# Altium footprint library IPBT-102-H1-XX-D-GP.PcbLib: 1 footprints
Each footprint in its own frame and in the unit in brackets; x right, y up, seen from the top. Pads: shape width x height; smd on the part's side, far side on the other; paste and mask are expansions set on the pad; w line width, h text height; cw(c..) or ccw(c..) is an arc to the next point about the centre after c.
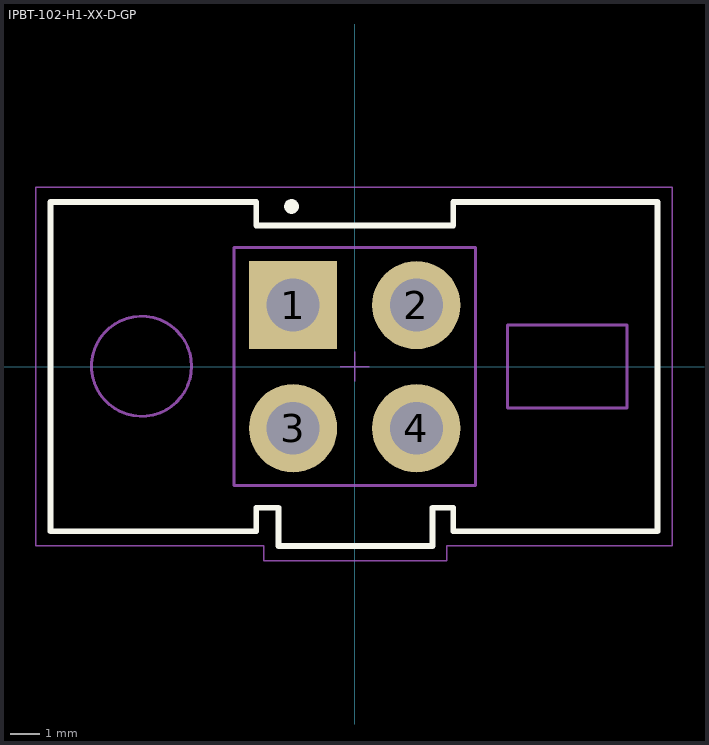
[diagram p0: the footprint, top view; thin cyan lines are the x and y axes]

## IPBT-102-H1-XX-D-GP [mm] "4.19mm pitch, power-mate header; double row"
height 10.29
pads (4):
  rect 3x3 / inner round 3 / far side rect 3x3 hole 1.8 mask+0: 1(-2.096,2.096)
  round 3 hole 1.8 mask+0: 2(2.095,2.096) 3(-2.096,-2.095) 4(2.095,-2.095)
Top Overlay:
  circle w0.25: c-2.15,5.45 r0.125
  lines w0.2: -10.35,-5.6 -3.35,-5.6 -3.35,-4.8 -2.6,-4.8 -2.6,-6.1 2.65,-6.1 2.65,-4.8 3.35,-4.8 3.35,-5.6 10.3,-5.6 10.3,5.6 3.35,5.6 3.35,4.8 -3.35,4.8 -3.35,5.6 -10.35,5.6 -10.35,-5.6
Mechanical 12:
  lines w0.001: -10.35,-5.6 -3.35,-5.6 -3.35,-4.8 -2.6,-4.8 -2.6,-6.1 2.65,-6.1 2.65,-4.8 3.35,-4.8 3.35,-5.6 10.3,-5.6 10.3,5.6 3.35,5.6 3.35,4.8 -3.35,4.8 -3.35,5.6 -10.35,5.6 -10.35,-5.6
Mechanical 13:
  circle w0.1: c-7.252,0.013 r1.702
  lines w0.1: -10.35,-5.6 -3.35,-5.6 -3.35,-4.8 -2.6,-4.8 -2.6,-6.1 2.65,-6.1 2.65,-4.8 3.35,-4.8 3.35,-5.6 10.3,-5.6 10.3,5.6 3.35,5.6 3.35,4.8 -3.35,4.8 -3.35,5.6 -10.35,5.6 -10.35,-5.6 ; -4.103,-4.051 4.102,-4.051 4.102,4.052 -4.103,4.052 -4.103,-4.051 ; 5.194,-1.409 9.258,-1.409 9.258,1.41 5.194,1.41 5.194,-1.409
  text ".Designator" at 0,0 h1.52
Mechanical 15:
  lines w0.05: -0.5,0 0.5,0 ; 0,-0.5 0,0.5 ; -10.85,-6.1 -3.1,-6.1 -3.1,-6.6 3.136,-6.6 3.136,-6.1 10.8,-6.1 10.8,6.1 -10.85,6.1 -10.85,-6.1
